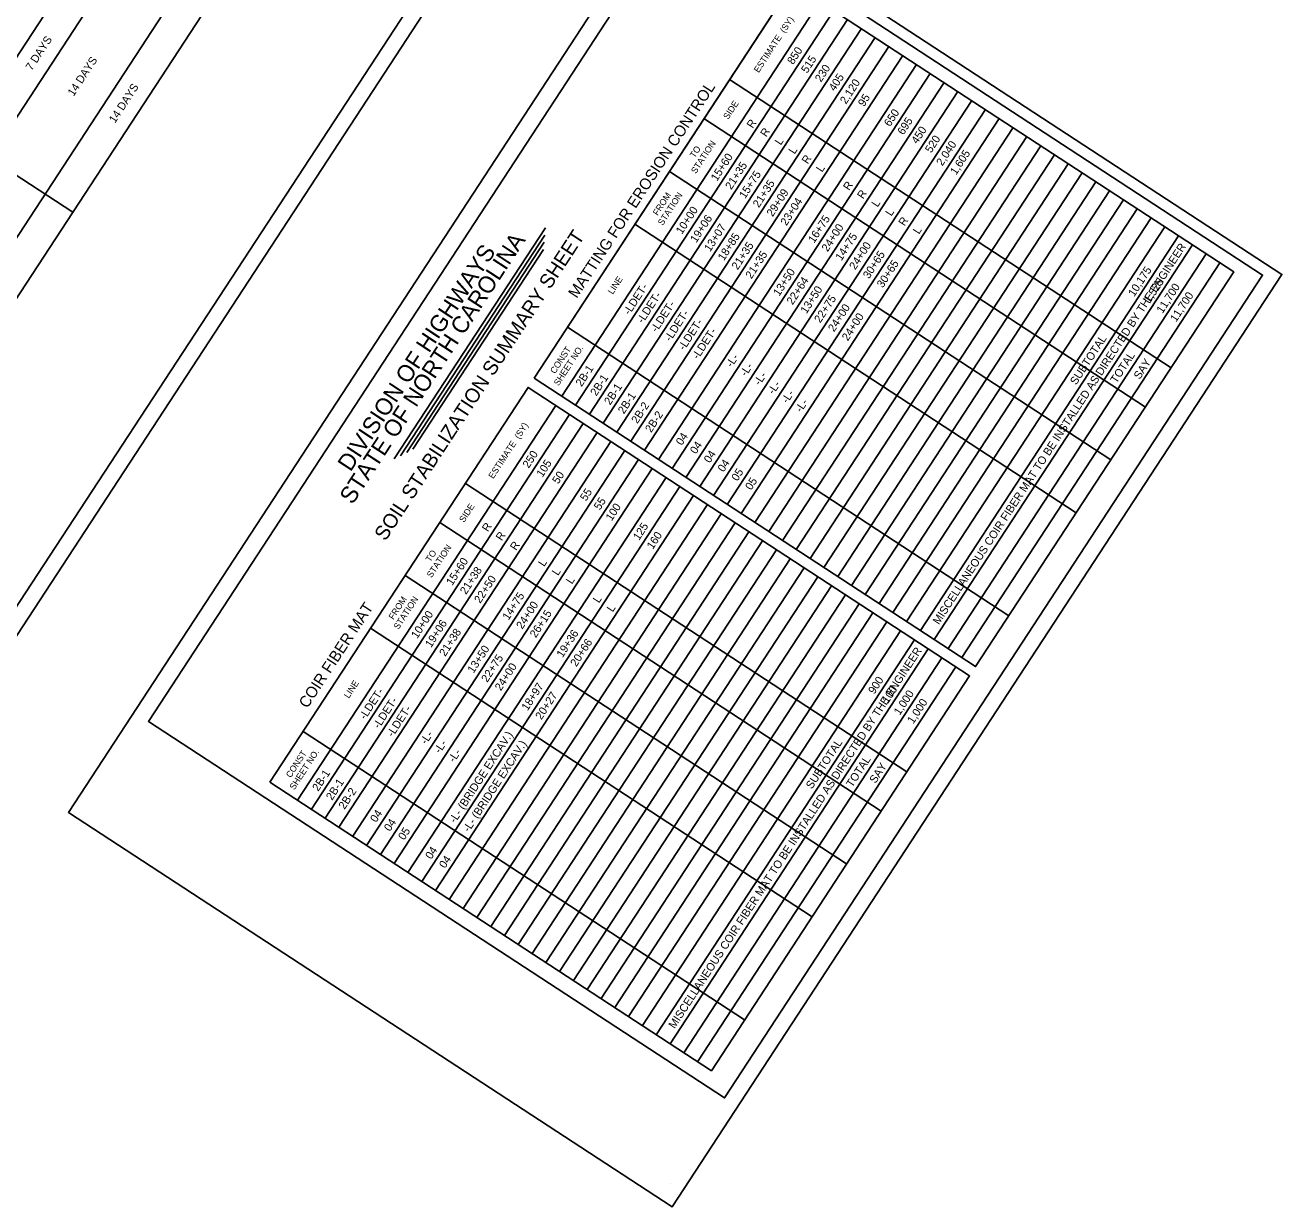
# Model space of a CAD drawing. Extents: x 1190029 to 2387899, y 163128 to 333969.
# Drawn here: x 2382621 to 2386455, y 327701 to 331307 of the extents above; entities that cross this region are included whole.
import ezdxf

# ---------------------------------------------------------------- set-up
doc = ezdxf.new("R2010")
doc.units = 0
for name, color, linetype in [('Matting Summary Sheet CELL', 7, 'Continuous'), ('Sheet_Plot_Border_Outside_CELL', 7, 'Continuous'), ('Stabilization Guidelines Sheet CELL', 7, 'Continuous')]:
    doc.layers.add(name, color=color, linetype=linetype)

msp = doc.modelspace()

# ---------------------------------------------------------------- linework, layer by layer
at = {"layer": 'Matting Summary Sheet CELL'}
for p, q in [((2384174.2, 330229.6), (2384961.8, 331434.4)), ((2384258.4, 330174.6), (2385046, 331379.4)), ((2384300.4, 330147.1), (2385088.1, 331351.9)), ((2384342.5, 330119.6), (2385130.1, 331324.3)), ((2384384.6, 330092.1), (2385172.2, 331296.8)), ((2384426.7, 330064.6), (2385214.3, 331269.3)), ((2384856.4, 331278.5), (2384856.4, 331278.5)), ((2384468.8, 330037.1), (2385256.4, 331241.8)), ((2384510.8, 330009.6), (2385298.5, 331214.3)), ((2384552.9, 329982), (2385340.5, 331186.8)), ((2384595, 329954.5), (2385382.6, 331159.3)), ((2384770.3, 331141.4), (2386116.9, 330261.1)), ((2384637.1, 329927), (2385424.7, 331131.8)), ((2384679.2, 329899.5), (2385466.8, 331104.3)), ((2384721.3, 329872), (2385508.9, 331076.7)), ((2384763.3, 329844.5), (2385550.9, 331049.2)), ((2384692.1, 331021.8), (2386038.7, 330141.5)), ((2384805.4, 329817), (2385593, 331021.7)), ((2384847.5, 329789.5), (2385635.1, 330994.2)), ((2384889.6, 329762), (2385677.2, 330966.7)), ((2384931.7, 329734.4), (2385719.3, 330939.2)), ((2384973.7, 329706.9), (2385761.4, 330911.7)), ((2385015.8, 329679.4), (2385803.4, 330884.2)), ((2384586.7, 330860.6), (2385933.3, 329980.3)), ((2385057.9, 329651.9), (2385845.5, 330856.7)), ((2385100, 329624.4), (2385887.6, 330829.1)), ((2385142.1, 329596.9), (2385929.7, 330801.6)), ((2385184.1, 329569.4), (2385971.8, 330774.1)), ((2385226.2, 329541.9), (2386013.8, 330746.6)), ((2385268.3, 329514.4), (2386055.9, 330719.1)), ((2383747.3, 329983.1), (2384208.2, 330688.2)), ((2384481.3, 330699.4), (2385827.9, 329819.1)), ((2385310.4, 329486.8), (2386098, 330691.6)), ((2383766, 329992.9), (2384206.3, 330666.4)), ((2383785.2, 330002.4), (2384204.9, 330644.3)), ((2385352.5, 329459.3), (2386140.1, 330664.1)), ((2383803.9, 330013.1), (2384202.5, 330622.8)), ((2385394.5, 329431.8), (2386182.2, 330636.6)), ((2385436.6, 329404.3), (2386224.2, 330609.1)), ((2385478.7, 329376.8), (2386266.3, 330581.5)), ((2384275.7, 330384.9), (2385622.3, 329504.5)), ((2384263.8, 330372), (2384263.8, 330372)), ((2384174.2, 330229.6), (2385520.8, 329349.3)), ((2384216.3, 330202.1), (2384216.3, 330202.1)), ((2384223.2, 330197.6), (2384223.2, 330197.6)), ((2383452.2, 328941.5), (2384239.8, 330146.3)), ((2384258.4, 330174.6), (2384258.4, 330174.6)), ((2384300.4, 330147.1), (2384300.4, 330147.1)), ((2383494.3, 328914), (2384281.9, 330118.8)), ((2384342.5, 330119.6), (2384342.5, 330119.6)), ((2383536.4, 328886.5), (2384324, 330091.2)), ((2384384.6, 330092.1), (2384384.6, 330092.1)), ((2384421, 330068.3), (2384421, 330068.3)), ((2383578.5, 328859), (2384366.1, 330063.7)), ((2383620.5, 328831.5), (2384408.1, 330036.2)), ((2384426.7, 330064.6), (2384426.7, 330064.6)), ((2384468.8, 330037.1), (2384468.8, 330037.1)), ((2383662.6, 328804), (2384450.2, 330008.7)), ((2384510.8, 330009.6), (2384510.8, 330009.6)), ((2383704.7, 328776.5), (2384492.3, 329981.2)), ((2383746.8, 328748.9), (2384534.4, 329953.7)), ((2384552.9, 329982), (2384552.9, 329982)), ((2384595, 329954.5), (2384595, 329954.5)), ((2383788.9, 328721.4), (2384576.5, 329926.2)), ((2384637.1, 329927), (2384637.1, 329927)), ((2384637.1, 329927), (2384637.1, 329927)), ((2383830.9, 328693.9), (2384618.6, 329898.7)), ((2383964.1, 329908.3), (2385310.7, 329028)), ((2384679.2, 329899.5), (2384679.2, 329899.5)), ((2383873, 328666.4), (2384660.6, 329871.2)), ((2383915.1, 328638.9), (2384702.7, 329843.7)), ((2384721.3, 329872), (2384721.3, 329872)), ((2384763.3, 329844.5), (2384763.3, 329844.5)), ((2383957.2, 328611.4), (2384744.8, 329816.1)), ((2384805.4, 329817), (2384805.4, 329817)), ((2384805.4, 329817), (2384805.4, 329817)), ((2383886, 329788.8), (2385232.6, 328908.4)), ((2383999.3, 328583.9), (2384786.9, 329788.6)), ((2384041.3, 328556.4), (2384829, 329761.1)), ((2384847.5, 329789.5), (2384847.5, 329789.5)), ((2384847.5, 329789.5), (2384847.5, 329789.5)), ((2384889.6, 329762), (2384889.6, 329762)), ((2384083.4, 328528.9), (2384871, 329733.6)), ((2384931.7, 329734.4), (2384931.7, 329734.4)), ((2384125.5, 328501.4), (2384913.1, 329706.1)), ((2384973.7, 329706.9), (2384973.7, 329706.9)), ((2384973.7, 329706.9), (2384973.7, 329706.9)), ((2384167.6, 328473.8), (2384955.2, 329678.6)), ((2384209.7, 328446.3), (2384997.3, 329651.1)), ((2385015.8, 329679.4), (2385015.8, 329679.4)), ((2385015.8, 329679.4), (2385015.8, 329679.4)), ((2385057.9, 329651.9), (2385057.9, 329651.9)), ((2383780.6, 329627.6), (2385127.2, 328747.2)), ((2384251.7, 328418.8), (2385039.4, 329623.6)), ((2385100, 329624.4), (2385100, 329624.4)), ((2384293.8, 328391.3), (2385081.4, 329596.1)), ((2385142.1, 329596.9), (2385142.1, 329596.9)), ((2385142.1, 329596.9), (2385142.1, 329596.9)), ((2385184.1, 329569.4), (2385184.1, 329569.4)), ((2385184.1, 329569.4), (2385184.1, 329569.4)), ((2384335.9, 328363.8), (2385123.5, 329568.5)), ((2384378, 328336.3), (2385165.6, 329541)), ((2385226.2, 329541.9), (2385226.2, 329541.9)), ((2385226.2, 329541.9), (2385226.2, 329541.9)), ((2384420.1, 328308.8), (2385207.7, 329513.5)), ((2385268.3, 329514.4), (2385268.3, 329514.4)), ((2383675.2, 329466.4), (2385021.8, 328586)), ((2384462.1, 328281.3), (2385249.8, 329486)), ((2384504.2, 328253.7), (2385291.9, 329458.5)), ((2385310.4, 329486.8), (2385310.4, 329486.8)), ((2385310.4, 329486.8), (2385310.4, 329486.8)), ((2385352.5, 329459.3), (2385352.5, 329459.3)), ((2385352.5, 329459.3), (2385352.5, 329459.3)), ((2384546.3, 328226.2), (2385333.9, 329431)), ((2385394.5, 329431.8), (2385394.5, 329431.8)), ((2385394.5, 329431.8), (2385394.5, 329431.8)), ((2384588.4, 328198.7), (2385376, 329403.5)), ((2385436.6, 329404.3), (2385436.6, 329404.3)), ((2384630.5, 328171.2), (2385418.1, 329376)), ((2384672.6, 328143.7), (2385460.2, 329348.5)), ((2385478.7, 329376.8), (2385478.7, 329376.8)), ((2385478.7, 329376.8), (2385478.7, 329376.8)), ((2385520.8, 329349.3), (2385520.8, 329349.3)), ((2385520.8, 329349.3), (2385520.8, 329349.3)), ((2382997, 329182.3), (2382997, 329182.3)), ((2383469.5, 329151.8), (2384816.1, 328271.4)), ((2383457.7, 329138.9), (2383457.7, 329138.9)), ((2383368, 328996.5), (2383368, 328996.5)), ((2383368, 328996.5), (2384714.6, 328116.2)), ((2383410.1, 328969), (2383410.1, 328969)), ((2383417.1, 328964.5), (2383417.1, 328964.5)), ((2383452.2, 328941.5), (2383452.2, 328941.5)), ((2383494.3, 328914), (2383494.3, 328914)), ((2383536.4, 328886.5), (2383536.4, 328886.5)), ((2383704.7, 328776.5), (2383704.7, 328776.5)), ((2383746.8, 328748.9), (2383746.8, 328748.9)), ((2383746.9, 328750.8), (2383746.9, 328750.8)), ((2383783.4, 328726.9), (2383783.4, 328726.9)), ((2383788.9, 328721.4), (2383788.9, 328721.4)), ((2383789, 328723.3), (2383789, 328723.3)), ((2383830.9, 328693.9), (2383830.9, 328693.9)), ((2383830.9, 328693.9), (2383830.9, 328693.9)), ((2383831.1, 328695.7), (2383831.1, 328695.7)), ((2383873, 328666.4), (2383873, 328666.4)), ((2383915.1, 328638.9), (2383915.1, 328638.9)), ((2383957.2, 328611.4), (2383957.2, 328611.4)), ((2383999.3, 328583.9), (2383999.3, 328583.9)), ((2383999.3, 328583.9), (2383999.3, 328583.9)), ((2384041.3, 328556.4), (2384041.3, 328556.4)), ((2384041.3, 328556.4), (2384041.3, 328556.4)), ((2384083.4, 328528.9), (2384083.4, 328528.9)), ((2384125.5, 328501.4), (2384125.5, 328501.4)), ((2384167.6, 328473.8), (2384167.6, 328473.8)), ((2384167.6, 328473.8), (2384167.6, 328473.8)), ((2384209.7, 328446.3), (2384209.7, 328446.3)), ((2384209.7, 328446.3), (2384209.7, 328446.3)), ((2384251.7, 328418.8), (2384251.7, 328418.8)), ((2384293.8, 328391.3), (2384293.8, 328391.3)), ((2384335.9, 328363.8), (2384335.9, 328363.8)), ((2384335.9, 328363.8), (2384335.9, 328363.8)), ((2384378, 328336.3), (2384378, 328336.3)), ((2384378, 328336.3), (2384378, 328336.3)), ((2384420.1, 328308.8), (2384420.1, 328308.8)), ((2384420.1, 328308.8), (2384420.1, 328308.8)), ((2384462.1, 328281.3), (2384462.1, 328281.3)), ((2384504.2, 328253.8), (2384504.2, 328253.8)), ((2384504.2, 328253.7), (2384504.2, 328253.7)), ((2384546.3, 328226.2), (2384546.3, 328226.2)), ((2384546.3, 328226.2), (2384546.3, 328226.2)), ((2384588.4, 328198.7), (2384588.4, 328198.7)), ((2384588.4, 328198.7), (2384588.4, 328198.7)), ((2384630.5, 328171.2), (2384630.5, 328171.2)), ((2384672.6, 328143.7), (2384672.6, 328143.7)), ((2384672.6, 328143.7), (2384672.6, 328143.7)), ((2384714.6, 328116.2), (2384714.6, 328116.2)), ((2384714.6, 328116.2), (2384714.6, 328116.2)), ((2384754.7, 328033.2), (2384754.7, 328033.2)), ((2384590.9, 327773.5), (2384590.9, 327773.5)), ((2384610.2, 327729.9), (2384610.2, 327729.9))]:
    msp.add_line(p, q, dxfattribs=at)
for points in [[(2384638.6, 331693.3), (2382997, 329182.3), (2384754.7, 328033.2), (2386396.3, 330544.2)], [(2384174.2, 330229.6), (2384961.8, 331434.4), (2386308.4, 330554), (2385520.8, 329349.3)], [(2383368, 328996.5), (2384155.7, 330201.3), (2385502.2, 329320.9), (2384714.6, 328116.2)]]:
    msp.add_lwpolyline(points, close=True, dxfattribs=at)
at = {"layer": 'Sheet_Plot_Border_Outside_CELL'}
for points in [[(2382408.3, 333179.5), (2380547.8, 330333.7), (2382389.2, 329129.9), (2384249.7, 331975.7)], [(2384613.6, 331750.3), (2382753.2, 328904.5), (2384594.6, 327700.7), (2386455.1, 330546.5)]]:
    msp.add_lwpolyline(points, close=True, dxfattribs=at)
at = {"layer": 'Stabilization Guidelines Sheet CELL'}
for p, q in [((2381815.2, 330016.9), (2383390.4, 332426.3)), ((2381899.4, 329961.9), (2383474.6, 332371.3)), ((2382067.9, 329851.7), (2383643.1, 332261.1)), ((2382152.1, 329796.6), (2383727.3, 332206)), ((2382766.4, 330736.2), (2382092.9, 331176.5))]:
    msp.add_line(p, q, dxfattribs=at)
msp.add_lwpolyline([(2382433.3, 333122.5), (2380791.8, 330611.6), (2382549.4, 329462.5), (2384190.9, 331973.4)], close=True, dxfattribs=at)

# ---------------------------------------------------------------- texts
at = {"layer": 'Matting Summary Sheet CELL'}
for s, height, rotation, p in [('ESTIMATE  (SY)', 19.525, 56.8248, (2384859, 331160.2)), ('850', 24.42, 56.8248, (2384964.2, 331185)), ('515', 24.42, 56.8248, (2385006.8, 331158.5)), ('230', 24.42, 56.8248, (2385049, 331131.1)), ('405', 24.42, 56.8248, (2385091, 331103.5)), ('2,120', 24.42, 56.8248, (2385125.3, 331064.1)), ('MATTING FOR EROSION CONTROL', 34.186, 56.8248, (2384304.2, 330471.3)), ('SIDE', 19.53, 56.8248, (2384765.7, 331017.4)), ('95', 24.42, 56.8248, (2385180.4, 331056.5)), ('650', 24.42, 56.8248, (2385259.6, 330995.4)), ('695', 24.42, 56.8248, (2385300.6, 330969.9)), ('R', 24.4, 56.8248, (2384840.8, 330990.1)), ('R', 24.4, 56.8248, (2384882.3, 330963.9)), ('450', 24.42, 56.8248, (2385342.8, 330942.5)), ('STATION', 19.53, 56.8248, (2384667.2, 330852)), ('L', 24.4, 56.8248, (2384926.2, 330939.1)), ('520', 24.42, 56.8248, (2385384.9, 330915)), ('2,040', 24.42, 56.8248, (2385419.1, 330875.5)), ('TO', 19.53, 56.8248, (2384663.6, 330900)), ('15+60', 24.42, 56.8248, (2384731.4, 330828.9)), ('L', 24.4, 56.8248, (2384968.3, 330911.6)), ('1,605', 24.42, 56.8248, (2385461.1, 330847.9)), ('21+35', 24.42, 56.8248, (2384775.3, 330803.1)), ('R', 24.4, 56.8248, (2385008.6, 330881.3)), ('L', 24.4, 56.8248, (2385052.4, 330856.5)), ('15+75', 24.42, 56.8248, (2384817.4, 330775.6)), ('21+35', 24.42, 56.8248, (2384859.4, 330748.1)), ('FROM ', 19.53, 56.8248, (2384550.8, 330724.1)), ('STATION', 19.53, 56.8248, (2384566.1, 330693.9)), ('29+09', 24.42, 56.8248, (2384901.6, 330720.6)), ('R', 24.4, 56.8248, (2385135, 330800.6)), ('R', 24.4, 56.8248, (2385177.7, 330774.7)), ('23+04', 24.42, 56.8248, (2384943.7, 330693.2)), ('L', 24.4, 56.8248, (2385221.5, 330749.9)), ('10+00', 24.42, 56.8248, (2384624.7, 330666.8)), ('19+06', 24.42, 56.8248, (2384668.6, 330641.1)), ('16+75', 24.42, 56.8248, (2385027.9, 330639.8)), ('L', 24.4, 56.8248, (2385263.6, 330722.4)), ('R', 24.4, 56.8248, (2385303.9, 330692.1)), ('SOIL STABILIZATION SUMMARY SHEET', 43.954, 56.8248, (2383720.2, 329730.3)), ('13+07', 24.42, 56.8248, (2384710.7, 330613.6)), ('24+00', 24.42, 56.8248, (2385069.3, 330613.7)), ('L', 24.4, 56.8248, (2385347.7, 330667.3)), ('STATE OF NORTH CAROLINA', 51.279, 56.8248, (2383619.9, 329841.6)), ('18+85', 24.42, 56.8248, (2384752.7, 330586)), ('21+35', 24.42, 56.8248, (2384794.8, 330558.5)), ('14+75', 24.42, 56.8248, (2385111.3, 330586.1)), ('24+00', 24.42, 56.8248, (2385153.5, 330558.7)), ('  DIVISION OF HIGHWAYS', 51.279, 56.5947, (2383592.8, 329909.8)), ('21+35', 24.42, 56.8248, (2384836.9, 330531)), ('30+65', 24.42, 56.8248, (2385195.5, 330531.1)), ('MISCELLANEOUS COIR FIBER MAT TO BE INSTALLED AS DIRECTED BY THE ENGINEER', 24.419, 56.8248, (2385408.7, 329475.9)), ('30+65', 24.42, 56.8248, (2385237.6, 330503.5)), ('10,175', 24.42, 56.8248, (2386004.5, 330476.5)), ('LINE', 19.53, 56.8248, (2384413.7, 330483.8)), ('13+50', 24.42, 56.8248, (2384921.3, 330477.9)), ('22+64', 24.42, 56.8248, (2384962.6, 330451.7)), ('1,525', 24.42, 56.8248, (2386051.7, 330456)), ('-LDET-', 24.42, 56.8248, (2384464.7, 330420.8)), ('13+50', 24.42, 56.8248, (2385004.7, 330424.2)), ('11,700', 24.42, 56.8248, (2386090.9, 330425.3)), ('11,700', 24.42, 56.8248, (2386132.2, 330399.1)), ('-LDET-', 24.42, 56.8248, (2384505.6, 330395)), ('-LDET-', 24.42, 56.8248, (2384547.7, 330367.5)), ('22+75', 24.42, 56.8248, (2385046.7, 330396.5)), ('24+00', 24.42, 56.8248, (2385088.9, 330369.1)), ('-LDET-', 24.42, 56.8248, (2384589.8, 330340)), ('24+00', 24.42, 56.8248, (2385131, 330341.6)), ('-LDET-', 24.42, 56.8248, (2384631.9, 330312.5)), ('-LDET-', 24.42, 56.8248, (2384673.9, 330285)), ('SUBTOTAL', 24.42, 56.8248, (2385827.4, 330207.1)), ('CONST', 19.53, 56.8248, (2384237.6, 330241.5)), ('SHEET NO.', 19.53, 56.8248, (2384248.5, 330204.7)), ('-L-', 24.42, 56.8248, (2384777.1, 330260.6)), ('TOTAL', 24.42, 56.8248, (2385950.5, 330212)), ('2B-1', 24.42, 56.8248, (2384318.8, 330201.9)), ('-L-', 24.42, 56.8248, (2384820.3, 330233.2)), ('SAY', 24.42, 56.8248, (2386021.4, 330224.2)), ('2B-1', 24.42, 56.8248, (2384363.7, 330173.5)), ('-L-', 24.42, 56.8248, (2384862.4, 330205.7)), ('2B-1', 24.42, 56.8248, (2384405.8, 330146)), ('2B-1', 24.42, 56.8248, (2384447.8, 330118.5)), ('-L-', 24.42, 56.8248, (2384904.5, 330178.2)), ('-L-', 24.42, 56.8248, (2384946.6, 330150.7)), ('2B-2', 24.42, 56.8248, (2384488.7, 330089.1)), ('-L-', 24.42, 56.8248, (2384988.6, 330123.2)), ('2B-2', 24.42, 56.8248, (2384530.8, 330061.6)), ('ESTIMATE  (SY)', 19.525, 56.8248, (2384049.2, 329921)), ('04', 24.42, 56.8248, (2384624.5, 330022.7)), ('04', 24.42, 56.8248, (2384667.8, 329996.3)), ('250', 24.42, 56.8248, (2384157.2, 329953)), ('04', 24.42, 56.8248, (2384709.9, 329968.8)), ('105', 24.42, 56.8248, (2384199.2, 329925.3)), ('04', 24.42, 56.8248, (2384752, 329941.3)), ('05', 24.42, 56.8248, (2384794, 329913.6)), ('50', 24.42, 56.8248, (2384247.4, 329904.9)), ('05', 24.42, 56.8248, (2384836.1, 329886.1)), ('55', 24.42, 56.8248, (2384332.3, 329852.7)), ('SIDE', 19.53, 56.8248, (2383960, 329787.8)), ('55', 24.42, 56.8248, (2384374.4, 329825.2)), ('100', 24.42, 56.8248, (2384410.4, 329792)), ('R', 24.4, 56.8248, (2384033.1, 329759)), ('125', 24.42, 56.8248, (2384493.8, 329732.8)), ('STATION', 19.53, 56.8248, (2383861.1, 329618.9)), ('R', 24.4, 56.8248, (2384075.2, 329731.5)), ('R', 24.4, 56.8248, (2384118.8, 329702)), ('160', 24.42, 56.8248, (2384535.9, 329705.4)), ('TO', 19.53, 56.8248, (2383857.5, 329666.9)), ('15+60', 24.42, 56.8248, (2383924, 329595)), ('21+38', 24.42, 56.8248, (2383966.1, 329567.5)), ('L', 24.4, 56.8248, (2384204.4, 329652.8)), ('22+50', 24.42, 56.8248, (2384009.4, 329540.8)), ('L', 24.4, 56.8248, (2384246.5, 329625.3)), ('L', 24.4, 56.8248, (2384289.1, 329599.3)), ('14+75', 24.42, 56.8248, (2384095.6, 329489.3)), ('COIR FIBER MAT', 34.186, 56.8248, (2383482.1, 329220)), ('FROM ', 19.53, 56.8248, (2383744.7, 329491)), ('STATION', 19.53, 56.8248, (2383759.9, 329460.8)), ('24+00', 24.42, 56.8248, (2384137.7, 329461.9)), ('L', 24.4, 56.8248, (2384371.5, 329541.6)), ('L', 24.4, 56.8248, (2384413.6, 329514.1)), ('10+00', 24.42, 56.8248, (2383817.3, 329433)), ('19+06', 24.42, 56.8248, (2383859.4, 329405.5)), ('26+15', 24.42, 56.8248, (2384179, 329435.5)), ('21+38', 24.42, 56.8248, (2383902.6, 329378.7)), ('19+36', 24.42, 56.8248, (2384260.6, 329374.9)), ('20+66', 24.42, 56.8248, (2384302.7, 329347.4)), ('13+50', 24.42, 56.8248, (2383988.9, 329327.3)), ('22+75', 24.42, 56.8248, (2384030.9, 329299.7)), ('MISCELLANEOUS COIR FIBER MAT TO BE INSTALLED AS DIRECTED BY THE ENGINEER', 24.419, 56.8248, (2384602.5, 328242.8)), ('24+00', 24.42, 56.8248, (2384072.3, 329273.6)), ('LINE', 19.53, 56.8248, (2383608.7, 329251)), ('18+97', 24.42, 56.8248, (2384153.9, 329212.9)), ('900', 24.42, 56.8248, (2385211.5, 329263.5)), ('-LDET-', 24.42, 56.8248, (2383658.7, 329185.7)), ('20+27', 24.42, 56.8248, (2384196, 329185.4)), ('100', 24.42, 56.8248, (2385253.5, 329235.1)), ('1,000', 24.42, 56.8248, (2385289.3, 329199.2)), ('-LDET-', 24.42, 56.8248, (2383700.8, 329158.2)), ('-LDET-', 24.42, 56.8248, (2383742.8, 329132.7)), ('1,000', 24.42, 56.8248, (2385330.6, 329172.9)), ('-L-', 24.42, 56.8248, (2383844.7, 329110)), ('-L- (BRIDGE EXCAV.)', 24.419, 56.8248, (2383932.8, 328870)), ('-L-', 24.42, 56.8248, (2383886.8, 329082.5)), ('-L- (BRIDGE EXCAV.)', 24.419, 56.8248, (2383974.9, 328842.5)), ('SUBTOTAL', 24.42, 56.8248, (2385021.3, 328974)), ('CONST', 19.53, 56.8248, (2383431.4, 329008.5)), ('SHEET NO.', 19.53, 56.8248, (2383442.4, 328971.6)), ('-L-', 24.42, 56.8248, (2383930, 329055.1)), ('2B-1', 24.42, 56.8248, (2383515.3, 328967.1)), ('TOTAL', 24.42, 56.8248, (2385144.4, 328978.9)), ('SAY', 24.42, 56.8248, (2385215.2, 328991.1)), ('2B-1', 24.42, 56.8248, (2383557.4, 328939.6)), ('2B-2', 24.42, 56.8248, (2383595.6, 328911.9)), ('04', 24.42, 56.8248, (2383692.1, 328872.1)), ('04', 24.42, 56.8248, (2383734.2, 328844.6)), ('05', 24.42, 56.8248, (2383777.4, 328818.1)), ('04', 24.42, 56.8248, (2383860.1, 328759.5)), ('04', 24.42, 56.8248, (2383902.2, 328732))]:
    msp.add_text(s, height=height, rotation=rotation, dxfattribs=at).set_placement(p)
at = {"layer": 'Stabilization Guidelines Sheet CELL'}
for s, p in [('7 DAYS', (2382641.1, 331166.4)), ('14 DAYS', (2382769.1, 331088.3)), ('14 DAYS', (2382895.1, 331006.3))]:
    msp.add_text(s, height=24.42, rotation=56.8248, dxfattribs=at).set_placement(p)

doc.saveas('drawing.dxf')
